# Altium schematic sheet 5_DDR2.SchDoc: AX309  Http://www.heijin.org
size OrCAD A; DocumentNumber: 5; SheetNumber: 5; SheetTotal: 7
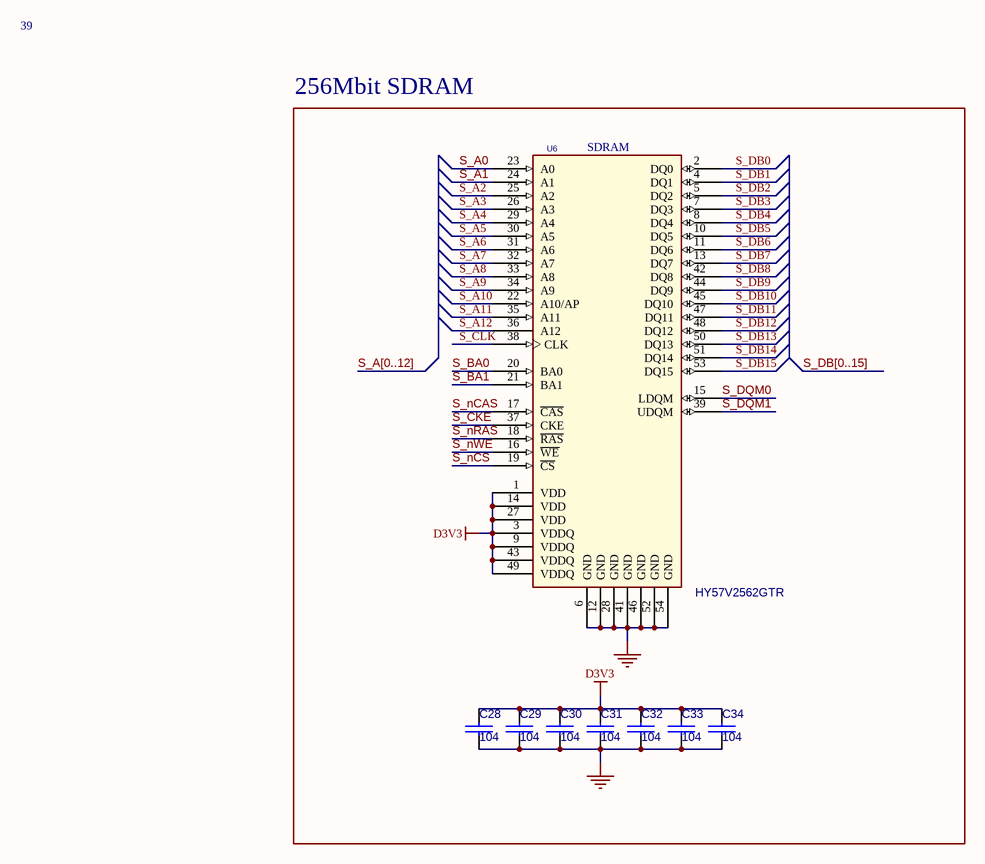
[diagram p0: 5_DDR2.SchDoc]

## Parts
C28  104  [0402]
C29  104  [0402]
C30  104  [0402]
C31  104  [0402]
C32  104  [0402]
C33  104  [0402]
C34  104  [0402]
U6  HY57V2562GTR  [TSOP-54]

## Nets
D3V3: C28.1 C29.1 C30.1 C31.1 C32.1 C33.1 C34.1 U6.1(VDD) U6.3(VDDQ) U6.9(VDDQ) U6.14(VDD) U6.27(VDD) U6.43(VDDQ) U6.49(VDDQ)
GND: C28.2 C29.2 C30.2 C31.2 C32.2 C33.2 C34.2 U6.6(GND) U6.12(GND) U6.28(GND) U6.41(GND) U6.46(GND) U6.52(GND) U6.54(GND)
S_A0: U6.23(A0)
S_A1: U6.24(A1)
S_A2: U6.25(A2)
S_A3: U6.26(A3)
S_A4: U6.29(A4)
S_A5: U6.30(A5)
S_A6: U6.31(A6)
S_A7: U6.32(A7)
S_A8: U6.33(A8)
S_A9: U6.34(A9)
S_A10: U6.22(A10/AP)
S_A11: U6.35(A11)
S_A12: U6.36(A12)
S_BA0: U6.20(BA0)
S_BA1: U6.21(BA1)
S_CKE: U6.37(CKE)
S_CLK: U6.38(CLK)
S_DB0: U6.2(DQ0)
S_DB1: U6.4(DQ1)
S_DB2: U6.5(DQ2)
S_DB3: U6.7(DQ3)
S_DB4: U6.8(DQ4)
S_DB5: U6.10(DQ5)
S_DB6: U6.11(DQ6)
S_DB7: U6.13(DQ7)
S_DB8: U6.42(DQ8)
S_DB9: U6.44(DQ9)
S_DB10: U6.45(DQ10)
S_DB11: U6.47(DQ11)
S_DB12: U6.48(DQ12)
S_DB13: U6.50(DQ13)
S_DB14: U6.51(DQ14)
S_DB15: U6.53(DQ15)
S_DQM0: U6.15(LDQM)
S_DQM1: U6.39(UDQM)
S_nCAS: U6.17(~{CAS})
S_nCS: U6.19(~{CS})
S_nRAS: U6.18(~{RAS})
S_nWE: U6.16(~{WE})

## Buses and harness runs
bus S_A[0..12]
bus S_DB[0..15]

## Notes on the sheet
- 39
- 256Mbit SDRAM
- (near U6) SDRAM

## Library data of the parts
C28-C34 = C_Dup2
U6 = HY57651620/SO_0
